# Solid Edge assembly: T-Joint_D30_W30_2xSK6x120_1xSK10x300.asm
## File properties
Author: fknapp
Template: iso metric assembly.asm
Last saved by: fknapp
Revision: 8
Application: Solid Edge
Username: fknapp
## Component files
T-Joint_D30_W30.par
SK Schraube 6x120_ohne_Gewinde.par
SK Schraube 10x300_ohne_Gewinde_22042020.par
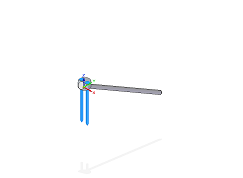
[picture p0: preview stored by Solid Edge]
